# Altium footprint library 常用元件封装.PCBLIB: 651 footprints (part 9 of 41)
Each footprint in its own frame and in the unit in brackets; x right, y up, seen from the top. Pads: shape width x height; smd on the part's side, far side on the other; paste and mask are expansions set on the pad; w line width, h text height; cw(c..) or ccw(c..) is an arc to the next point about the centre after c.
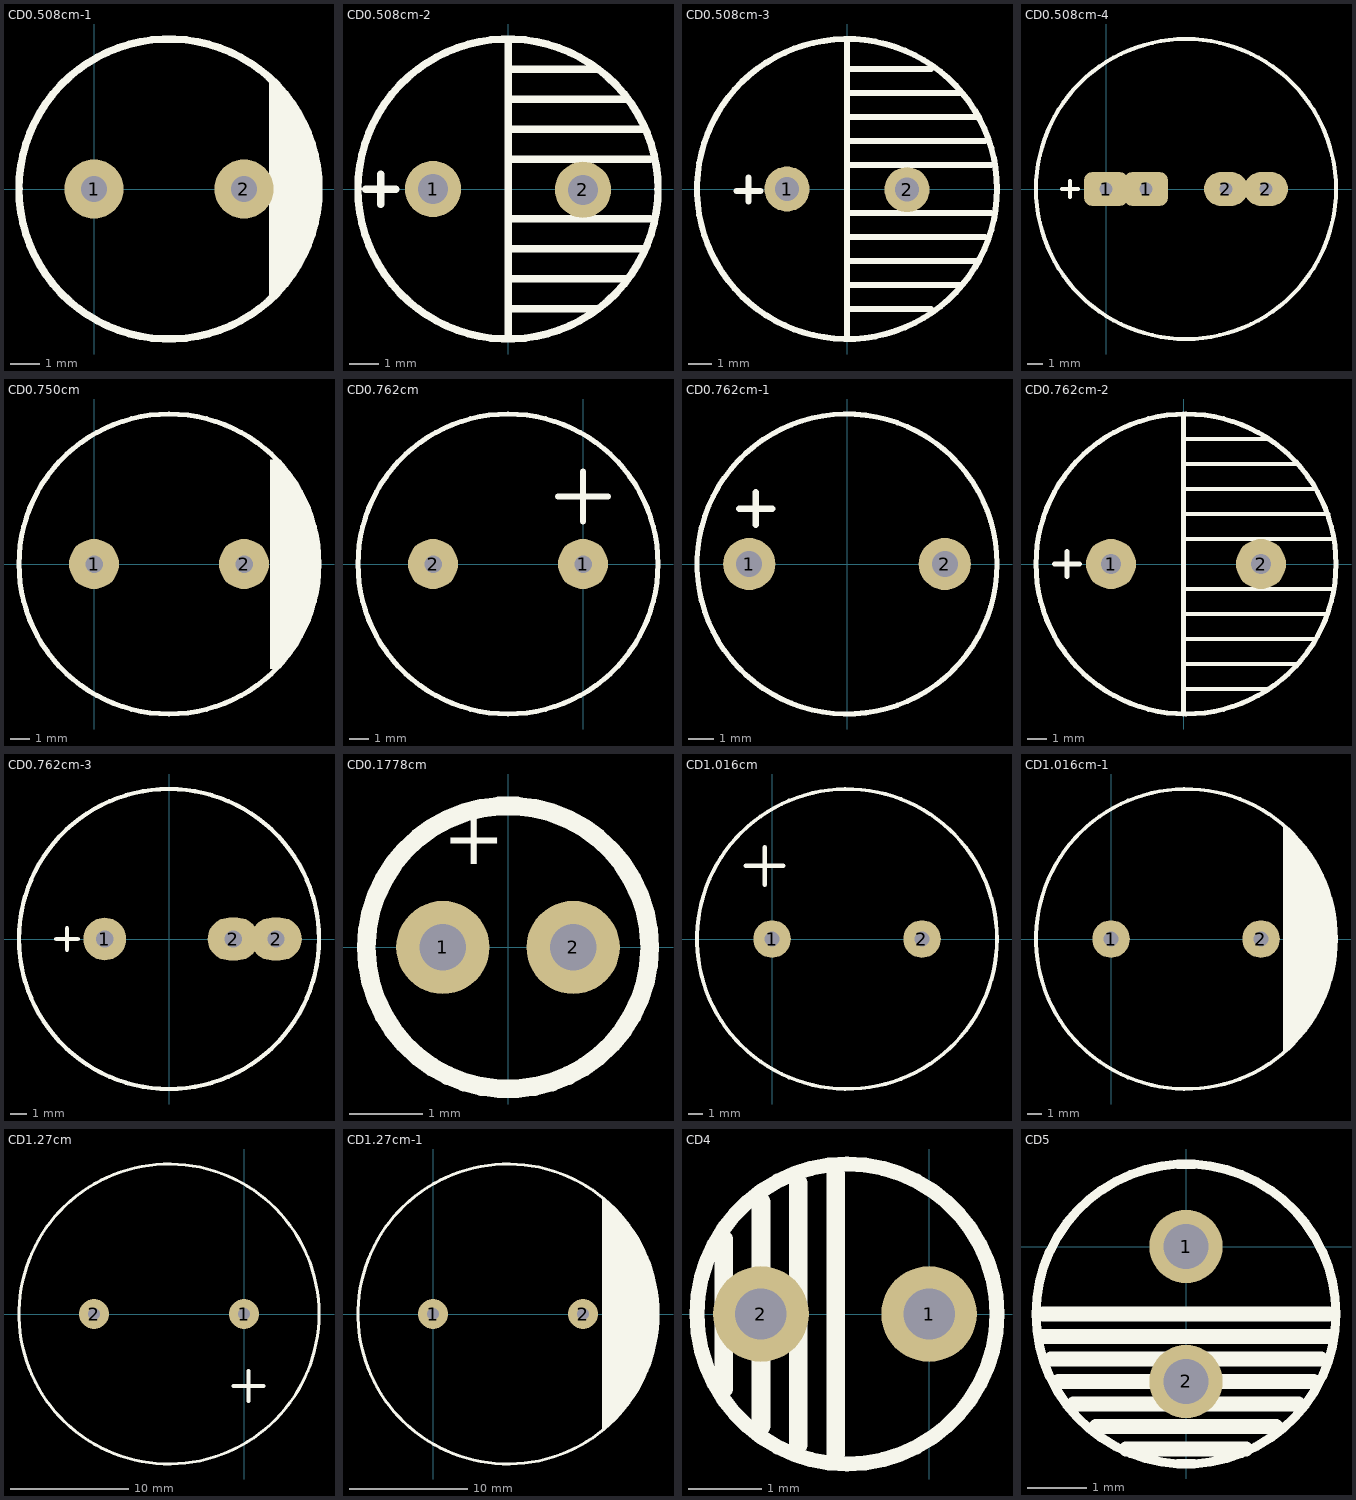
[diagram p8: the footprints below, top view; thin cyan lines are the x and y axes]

## CD0.508cm-1 [mm] "10.16mmX5.08mm"
pads (2):
  round 2 hole 0.889: 1(0,0) 2(5.08,0)
TopOverlay:
  circle w0.254: c2.54,0 r5.08
  region: 6.147,3.708 5.918,3.708 5.918,-3.708 6.147,-3.708
  region: 7.518,1.372 7.29,1.372 7.29,-1.372 7.518,-1.372
  region: 7.315,1.956 7.087,1.956 7.087,-1.981 7.315,-1.981
  region: 7.112,2.438 6.833,2.438 6.833,-2.413 7.112,-2.413
  region: 6.883,2.794 6.553,2.794 6.553,-2.794 6.883,-2.794
  region: 6.629,3.175 6.375,3.175 6.375,-3.2 6.629,-3.2
  region: 6.401,3.404 6.121,3.404 6.121,-3.429 6.401,-3.429

## CD0.508cm-2 [mil] "10.16mmX5.08mm"
pads (2):
  round 75 hole 40: 1(-100,0) 2(100,-1)
TopOverlay:
  circle w10: c0,0 r200
  lines w10: -190,0 -150,0 ; -170,-20 -170,20 ; 0,-200 0,200 ; 0,-160 120,-160 ; 0,-120 160,-120 ; 0,-80 180,-80 ; 0,-40 190,-40 ; 0,40 190,40 ; 0,80 180,80 ; 0,120 160,120 ; 0,160 120,160

## CD0.508cm-3 [mil] "12.7mmX5.08mm"
pads (2):
  round 75 hole 40: 1(-100,0) 2(100,-1)
TopOverlay:
  circle w10: c0,0 r250
  lines w10: -184,-3 -144,-3 ; -164,-21 -164,19 ; 0,-250 0,250 ; 0,-200 140,-200 ; 0,-160 190,-160 ; 0,-120 220,-120 ; 0,-80 230,-80 ; 0,-40 240,-40 ; 0,40 240,40 ; 0,80 230,80 ; 0,120 220,120 ; 0,160 190,160 ; 0,200 140,200

## CD0.508cm-4 [mil] "19mmX10.16mmX5.08mm"
pads (4):
  rrect50% 110x85 hole 32: 1(0,0) 1(100,0)
  oval 110x85 hole 32: 2(300,0) 2(400,0)
TopOverlay:
  circle w10: c200,0 r375
  lines w10: -110,0 -70,0 ; -90,-20 -90,20

## CD0.750cm [mil] "15.24mmX7.5mm"
pads (2):
  round 100 hole 35: 1(0,0) 2(300,0)
TopOverlay:
  circle w10: c150,0 r300
  region: 448,59 438,59 438,-59 448,-59
  region: 439,94 429,94 429,-94 439,-94
  region: 430,120 419,120 419,-122 430,-122
  region: 420,140 409,140 409,-142 420,-142
  region: 410,157 400,157 400,-157 410,-157
  region: 400,173 388,173 388,-173 400,-173
  region: 389,188 377,188 377,-189 389,-189
  region: 378,200 367,200 367,-198 378,-198
  region: 368,209 352,209 352,-210 368,-210

## CD0.762cm [mil] "15.24mm7.62mm"
pads (2):
  round 100 hole 35: 1(0,0) 2(-300,0)
TopOverlay:
  circle w10: c-150,0 r300
  lines w12: -50,135 50,135 ; 0,85 0,185

## CD0.762cm-1 [mil] "11.68mm7.62mm"
pads (2):
  round 80 hole 40: 1(-150,0) 2(150,0)
TopOverlay:
  circle w8: c0,0 r230
  lines w10: -165,85 -115,85 ; -140,60 -140,110

## CD0.762cm-2 [mil] "15.24mm7.62mm"
pads (2):
  round 100 hole 40: 1(-145,0) 2(155,0)
TopOverlay:
  circle w10: c5,0 r300
  lines w8: 0,-250 170,-250 ; 0,-200 230,-200 ; 0,-150 265,-150 ; 0,-100 285,-100 ; 0,-50 300,-50 ; 0,50 300,50 ; 0,100 290,100 ; 0,150 260,150 ; 0,200 230,200 ; 0,250 170,250
  lines w10: -258,0 -208,0 ; -233,-25 -233,25 ; 0,-300 0,300

## CD0.762cm-3 [mil] "17.78mmX10.16mmX7.62mm"
pads (3):
  round 100 hole 40: 1(-150,0)
  oval 120x100 hole 40: 2(150,0) 2(250,0)
TopOverlay:
  circle w10: c0,0 r350
  lines w10: -263,0 -213,0 ; -238,-25 -238,25

## CD0.1778cm [mil] "3.8mmx1.778mm"
pads (2):
  round 50 hole 25: 1(-35,0) 2(35,0)
TopOverlay:
  circle w10: c0,0 r76
  text "+" at -35,35 h50

## CD1.016cm [mil] "20.32mm10.16mm"
pads (2):
  round 100 hole 40: 1(0,0) 2(400,0)
TopOverlay:
  circle w10: c200,0 r400
  lines w12: -70,195 30,195 ; -20,145 -20,245

## CD1.016cm-1 [mil] "20.32mm10.16mm"
pads (2):
  round 100 hole 40: 1(0,0) 2(400,0)
TopOverlay:
  circle w10: c200,0 r400
  region: 472,300 458,300 458,-299 472,-299
  region: 485,286 470,286 470,-287 485,-287
  region: 497,274 484,274 484,-274 497,-274
  region: 508,261 496,261 496,-261 508,-261
  region: 518,250 506,250 506,-248 518,-248
  region: 528,235 517,235 517,-237 528,-237
  region: 538,221 527,221 527,-221 538,-221
  region: 548,205 537,205 537,-205 548,-205
  region: 557,188 547,188 547,-188 557,-188
  region: 566,170 556,170 556,-171 566,-171
  region: 575,149 565,149 565,-149 575,-149
  region: 584,127 574,127 574,-127 584,-127
  region: 593,93 583,93 583,-93 593,-93
  region: 599,42 589,42 589,-45 599,-45

## CD1.27cm [mil] "25.4mmX12.7mm"
pads (2):
  round 100 hole 40: 1(0,0) 2(-500,0)
TopOverlay:
  circle w10: c-250,0 r500
  lines w12: -35,-240 65,-240 ; 15,-290 15,-190

## CD1.27cm-1 [mil] "25.4mmX12.7mm"
pads (2):
  round 100 hole 40: 1(0,0) 2(500,0)
TopOverlay:
  circle w10: c250,0 r500
  region: 579,383 563,383 563,-383 579,-383
  region: 593,370 578,370 578,-370 593,-370
  region: 607,357 592,357 592,-357 607,-357
  region: 620,343 606,343 606,-343 620,-343
  region: 633,329 619,329 619,-329 633,-329
  region: 645,314 632,314 632,-314 645,-314
  region: 656,299 644,299 644,-299 656,-299
  region: 667,284 655,284 655,-284 667,-284
  region: 678,267 666,267 666,-267 678,-267
  region: 689,249 677,249 677,-249 689,-249
  region: 699,229 688,229 688,-229 699,-229
  region: 709,209 698,209 698,-209 709,-209
  region: 719,186 708,186 708,-186 719,-186
  region: 729,158 718,158 718,-159 729,-159
  region: 738,125 728,125 728,-125 738,-125
  region: 746,83 737,83 737,-81 746,-81

## CD4 [mm]
pads (2):
  round 1.3 hole 0.7: 1(0,0) 2(-2.286,0)
TopOverlay:
  circle w0.203: c-1.116,0 r2.04
  lines w0.254: -2.794,-1.016 -2.794,1.016 ; -2.286,-1.524 -2.286,1.524 ; -1.778,-1.778 -1.778,1.778 ; -1.27,-1.905 -1.27,1.905

## CD5 [mm]
pads (2):
  round 1.24 hole 0.762: 1(0,0) 2(0,-2.286)
TopOverlay:
  circle w0.154: c0,-1.143 r2.54
  lines w0.254: -2.413,-1.524 2.413,-1.524 ; -2.413,-1.143 2.413,-1.143 ; -2.286,-1.905 2.286,-1.905 ; -2.159,-2.286 2.159,-2.286 ; -1.905,-2.667 1.905,-2.667 ; -1.524,-3.048 1.524,-3.048 ; -1.016,-3.429 1.016,-3.429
